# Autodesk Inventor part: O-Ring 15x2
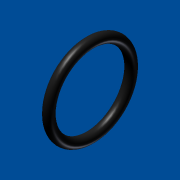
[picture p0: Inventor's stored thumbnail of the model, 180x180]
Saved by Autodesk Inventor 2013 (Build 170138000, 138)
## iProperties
Shininess: 41.0
Length Units: 11269
Angle Units: 11279
Time Units: 11290
Mass Units: 11283
Length Display Precision: 3
Angle Display Precision: 2
Created: 2001-04
Part Number: O-Ring 15x2
Material: Standard
Document SubType Name: Modellieren
Designer: dl
Density: 1 g/cm^3
Density: 0.0
Volumn: 0.0
Area: 0.0
PropertySet Name: Model Information
Control State: 0
Master: False
Checked Out: False
Author: dl
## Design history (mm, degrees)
body "Solid1"
revolve "Revolution1" stored, may be unused: angle "d2" = 90 deg
sketch "Sketch1"
  geometry: L1 (-12.454, 4.131)-(-10.51, 4.131); C1 r 1 at (-11.968, 12.631)
  constraints: 2 end point, 1 centre point, 1 horizontal
  dimensions: "d0" = 2 diameter of C1; "d1" = 8.5 vertical distance of L1.end C1.centre
